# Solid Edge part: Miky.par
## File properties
Title: Miky 40 40x32 cm
Author: DESYS
Template: Normal.par
Last saved by: Luca
Revision: 7
Application: Solid Edge
Tipo di contenuto documento: 0
Precisione: 0,990
Document Number: 8090
Revision: 0
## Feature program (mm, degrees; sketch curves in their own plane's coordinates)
sketch for "unnamed Protrusion 1" plane through (0, 0, 0) normal (0, 0, 1) x-axis (1, 0, 0)
  line (-233.5, -152.5) -> (233.5, -152.5)
  line (233.5, -152.5) -> (233.5, 152.5)
  line (233.5, 152.5) -> (-233.5, 152.5)
  line (-233.5, 152.5) -> (-233.5, -152.5)
  dimension (linear) = 233.5
  dimension (linear) = 233.5
extrude "unnamed Protrusion 1" add finite 12 along -normal
sketch for "ExtrudedProtrusion_2" plane through (0, 0, -12) normal (0, 0, -1) x-axis (1, 0, 0)
  line (-205, -145.5) -> (205, -145.5)
  line (205, -145.5) -> (205, 152.5)
  line (205, 152.5) -> (-205, 152.5)
  line (-205, 152.5) -> (-205, -145.5)
  dimension (linear) = 205
  dimension (linear) = 205
extrude "ExtrudedProtrusion_2" add finite 193 along +normal  Treatment1_DraftAngle = 3 deg
sketch for "ExtrudedCutout_1" plane through (0, 0, 0) normal (0, 0, 1) x-axis (-1, 0, 0)
  line (-203.5, -115.2722) -> (203.5, -115.2722)
  line (203.5, -115.2722) -> (203.5, 138.5)
  line (203.5, 138.5) -> (-203.5, 138.5)
  line (-203.5, 138.5) -> (-203.5, -115.2722)
  dimension (linear) = 203.5
extrude "ExtrudedCutout_1" cut finite 155 along -normal  Treatment1_DraftAngle = 6 deg
sketch for "Foro_1" plane through (0, -11.6139, -155) normal (0, 0, 1) x-axis (0, 1, 0)
  hole centre (44.1139, 0) bore radius 25
hole "Foro_1" diameter 50 through
sketch for "Foro_2" plane through (0, 0, 0) normal (0, -1, 0) x-axis (1, 0, 0)
  hole centre (0, -45) bore radius 10
hole "Foro_2" diameter 20 through
sketch for "ExtrudedCutout_2" plane through (0, -3.5, -205) normal (0, 0, -1) x-axis (1, 0, 0)
  line (-167.5, -111) -> (167.5, -111)
  line (167.5, -111) -> (167.5, 104)
  line (167.5, 104) -> (-167.5, 104)
  line (-167.5, 104) -> (-167.5, -111)
  dimension (linear) = 167.5
  dimension (linear) = 167.5
extrude "ExtrudedCutout_2" cut finite 40 along -normal  Treatment1_DraftAngle = 10 deg
sketch for "unnamed Cutout 1" plane through (0, 152.5, -6) normal (0, 1, 0) x-axis (1, 0, 0)
  line (-65, 199) -> (65, 199)
  line (65, 159) -> (65, 199)
  line (-65, 159) -> (65, 159)
  line (-65, 199) -> (-65, 159)
extrude "unnamed Cutout 1" cut through along -normal
fillet "Rotondo_1" radius 25
draft "Draft_1"  Angles1 = 6 deg
sketch for "ExtrudedProtrusion_3" #1 plane through (0, 6.6553, -165) normal (0, 0, -1) x-axis (1, 0, 0)
  circle centre (0, -25.8447) radius 25
sketch for "ExtrudedProtrusion_3" #2 plane through (0, 6.6553, -165) normal (0, 0, -1) x-axis (1, 0, 0)
  circle centre (0, -25.8447) radius 35
extrude "ExtrudedProtrusion_3" add finite 40 along +normal
sketch for "ExtrudedProtrusion_4" plane through (0, 0, 0) normal (1, 0, 0) x-axis (0, 1, 0)
  line (146.1289, 0) -> (167.5, 0)
  line (167.5, 0) -> (155.9706, -180.2081)
  line (155.9706, -180.2081) -> (59.6902, -201.5606)
  line (59.6902, -201.5606) -> (59.6902, -165)
  line (59.6902, -165) -> (110.1432, -165)
  line (110.1432, -165) -> (139.0788, -134.5241)
  line (139.0788, -134.5241) -> (146.1289, 0)
extrude "ExtrudedProtrusion_4" add finite 38 symmetric
fillet "Rotondo_2" radius 10
fillet "Rotondo_3" radius 15
fillet "Rotondo_4" radius 5
fillet "Rotondo_6" radius 10
fillet "Rotondo_7" radius 5
fillet "Rotondo_8" radius 5
fillet "Rotondo_9" radius 5
fillet "Rotondo_10" radius 5
fillet "Rotondo_11" radius 20
fillet "Rotondo_12" radius 15
fillet "Rotondo_13" radius 10
sketch for "Foro_3" plane through (0, -3.5, -205) normal (0, 0, -1) x-axis (1, 0, 0)
  hole centre (180.1336, -124.1336) bore radius 5
hole "Foro_3" diameter 10 finite
sketch for "unnamed Hole 1" plane through (0, -3.5, -205) normal (0, 0, -1) x-axis (1, 0, 0)
  hole centre (-180.1336, -124.1336) bore radius 5
  dimension (linear) = 180.1336
hole "unnamed Hole 1" finite
sketch for "Foro_5" plane through (0, -3.5, -205) normal (0, 0, -1) x-axis (1, 0, 0)
  hole centre (180.1336, 124.1336) bore radius 3
hole "Foro_5" diameter 6 finite
sketch for "unnamed Hole 2" plane through (0, -3.5, -205) normal (0, 0, -1) x-axis (1, 0, 0)
  hole centre (-180.1336, 124.1336) bore radius 3
hole "unnamed Hole 2" finite
pattern "unnamed Pattern 1" of "Foro_3", "unnamed Hole 1"
pattern "unnamed Pattern 2" of "Foro_5", "unnamed Hole 2"
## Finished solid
Body 1: solid body, 189 faces, 402 edges, 214 vertices.
  Faces by surface: cylinder 81, blend 43, plane 37, sphere 20, torus 8
  Edges by curve: line 158, circle 150, ellipse 50, intersection 44
Bounding box of the edges (mm; curved faces can reach further): 467.000 x 319.340 x 205.000, from (-233.5, -152.5, -205) to (233.5, 166.8398, 0).
Cylindrical faces by radius (mm): R3 x2, R5 x37, R10 x26, R15 x4, R20 x8, R25 x3, R35 x1
Toroidal faces (ring radius, tube radius in mm): R5 r5 x2, R30 r5 x4, R40 r15 x1, R45 r10 x1
Spherical faces by radius (mm): R5 x8, R10 x8, R20 x4
Planar faces by outward normal: +x 2, +y 2, +z 2, -x 2, -y 1, -z 9, oblique 19
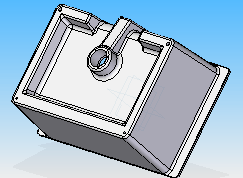
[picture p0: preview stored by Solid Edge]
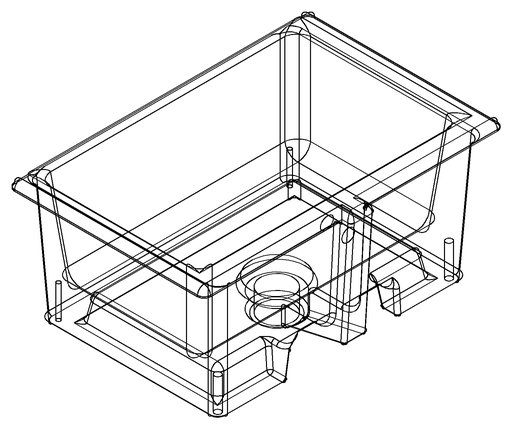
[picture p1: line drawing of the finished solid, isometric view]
